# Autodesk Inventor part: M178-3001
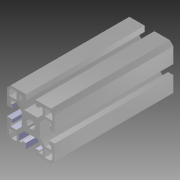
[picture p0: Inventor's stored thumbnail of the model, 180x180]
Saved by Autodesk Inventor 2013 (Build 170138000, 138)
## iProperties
Created: 2004-10
Material: Aluminium - 6061
Document SubType Name: Modeling
Designer: Autodesk, Inc.
Manufacturer: Standard
Standards Organization: Custom
Description: HUTCH, UPRIGHT
Stock Number: 10-040
Catalog Web Link: http://www.parker.com/ead/cm1.asp?cmid=809
Vendor: PARKER IPS
Part Number: M178-3001
Mass: 179.948 g
Surface Area: 483.565 cm^2
Volume: 66.4013 cm^3
Density: 2.71 g/cm^3
CAGE: 1LJX3
Dept. ID: Product Design
Description #2: ---
Finish #1: ---
Finish #2: ---
Material ID: ---
Project Number: ---
Length: 1219.200 mm
Author: Autodesk, Inc.
Revision Number: A
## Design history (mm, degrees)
derived "40 Series Profiles.ipt"
thread "Thread1" dims "d0" = 25, "d1" = 0
body "Solid1"
tag "TaggingFeature2"
feature "Solid1::40 Series Profiles.ipt" dims "ScaleForDerivedMember" = 10
other parameters: "Length" = 1219.2
